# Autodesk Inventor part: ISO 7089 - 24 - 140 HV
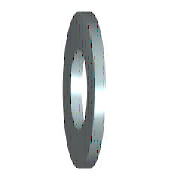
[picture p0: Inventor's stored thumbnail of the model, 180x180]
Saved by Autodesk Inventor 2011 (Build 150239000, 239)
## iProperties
IsCustomPart: 0
Created: 2009-02
Part Number: ISO 7089 - 24 - 140 HV
Material: Stainless Steel
Description: Plain washers - Normal series - Product grade A
Document SubType Name: Modeling
Standard: ISO 7089
Designer: V.de Jong
Standard Revision: Second edition 2000-06-01
Standards Organization: ISO
Language: en-US
Size Designation: 24 - 140 HV
Categories: <MemberInstance><Categories><Category DisplayName="Fasteners" InternalName="e4da775c-781d-43d5-af7c-5136215cf5a6" Mnemonic="FSTN"><Category DisplayName="Washers
Density: 8.08 g/cm^3
Mass: 33.2785 g
Surface Area: 29.2639 cm^2
Volume: 4.11863 cm^3
Author: V.de Jong
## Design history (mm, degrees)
body "Solid1"
sketch "Sketch"
  geometry: C1 r 22 at (0, 0); C2 r 12.5 at (0, 0); 1 further point
  constraints: 2 centre point, 2 coincident
  dimensions: "d0" = 25 diameter of C2 (= SD1); "d1" = 44 diameter of C1 (= SD2)
extrude "Body" new body sketch "Sketch" distance "d2" = 4 (= SD); taper "d3" = 0 deg
workaxis "Work Axis1"
workplane "Work Plane1"
other parameters: "SD1" = 25 [user parameter; used in 1 equation term], "SD2" = 44 [user parameter; used in 1 equation term], "SD" = 4 [user parameter; used in 1 equation term], "d4" = 0, "d5" = 0, "d6" = 0, "d7" = 0, "NND" = 24 [user parameter]
